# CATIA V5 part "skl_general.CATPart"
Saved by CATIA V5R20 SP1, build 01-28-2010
Part number: skl_general
Publications: "Plan_ref", "Point_ref", "Point_a2", "PointA", "PointD", "PointE", "PointB", "segment_Pt_ref_a2", "Point_projection_sur_axe_glissiere", "Point_projete", "axe_ref", "Plan_ortho_ref", "Plan_ortho_ref_bis", "Point_entraxe"
Bounding box of the stored display mesh (mm): x 0 to 40, y -50 to 400, z -220 to 30
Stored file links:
  C:\Users\Fabien-port\Desktop\test\skl_general.CATPart
  C:\Users\Fabien-port\Desktop\test\mecanisme_a_coulisseau.CATProduct
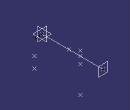
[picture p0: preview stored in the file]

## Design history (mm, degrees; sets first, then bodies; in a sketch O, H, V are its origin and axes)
External parameters (linked from other documents)
  External.longueur_guidage_coulisseau = 400 mm
  External.decalage_bati = 50 mm
  External.entraxe_coulisseau_bati = 220 mm
  External.longueur_AD = 300 mm
  External.longueur_ED = 250 mm
  External.rapport_BD_sur_ED = 0.7
  External.longueur_bielle3 = 80 mm
  External.decalage_bati.1 = 50 mm
  External.distance_Pt_projete = 74.162 mm
  External.entraxe_manivelle = 70 mm
Set1
  Plane1 "Plan_ref": type Offset, RefPlane yz-plane, Offset 0
  Point1 "Point_ref": (0, 0, 0)
  Point2 "Point_a2": (0, 400 {= External.longueur_guidage_coulisseau}, 0), relative to Point1
  Point3 "PointA": (0, -50 {= -External.decalage_bati}, -220 {= -External.entraxe_coulisseau_bati}), relative to Point1
  Point4 "PointD": (0, 300 {= External.longueur_AD}, 0), relative to Point3
  Point5 "PointE": (0, 0, 250 {= External.longueur_ED}), relative to Point4
  Point6 "PointB": type Between, FirstPoint Point4, SecondPoint Point5, Ratio 0.7 {= External.rapport_BD_sur_ED}
  Line1 "segment_Pt_ref_a2": type PtPt, FirstPoint Point1, SecondPoint Point2
  Point7 "Point_projection_sur_axe_glissiere": type OnCurve, Support Line1, RefPoint Point1, Length 250 {= -External.decalage_bati +External.longueur_AD}
  Point8 "Point_projete": type OnCurve, Support Line1, RefPoint Point7, Length 74.162 {= External.distance_Pt_projete}
  Line2 "axe_ref": type PtDir, RefPoint Point1, Direction Plane1, Start 40, End 20
  Plane2 "Plan_ortho_ref": type Offset, RefPlane zx-plane, Offset 0
  Plane3 "Plan_ortho_ref_bis": type Offset, RefPlane Plane2, Offset 400 {= External.longueur_guidage_coulisseau}
  Point9 "Point_entraxe": (0, 0, 70 {= External.entraxe_manivelle}), relative to Point3
Body1 (main body)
